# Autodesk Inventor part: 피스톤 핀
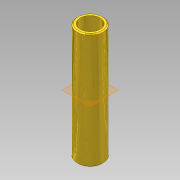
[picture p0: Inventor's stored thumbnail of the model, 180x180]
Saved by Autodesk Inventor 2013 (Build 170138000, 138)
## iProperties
Manager: KYOUNG IL JANG
Company: 한국ATC센터
Created: 2012-10
Part Number: 피스톤 핀
Document SubType Name: Modeling
Density: 1 g/cm^3
Checked By: KYOUNG IL JANG
Vendor: CBT Solutions
Designer: KYOUNG IL JANG
Material: 일반
Author: KYOUNG IL JANG
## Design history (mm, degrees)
sketch "스케치1"
  geometry: C1 r 6.5 at (0, 0); C2 r 5 at (0, 0); 1 further point
  constraints: 2 centre point, 2 coincident
  dimensions: "d0" = 13 diameter of C1; "d1" = 1.5 radial gap between concentric circles of C1 C2
extrude "돌출1" new body sketch "스케치1" stored distance "d2" = 58; taper "d3" = 0 deg
chamfer "모따기1" distance "d4" = 0.5; stored, may be unused: second distance "d5" = 2, angle "d6" = 45 deg
node "솔리드1"
